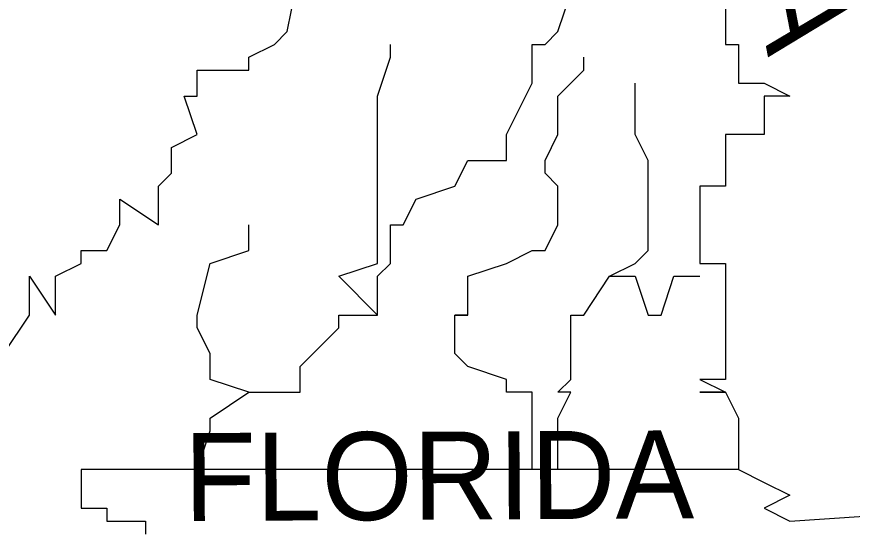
# Model space of a CAD drawing. Extents: x 515543 to 517243, y 661761 to 662861.
# Drawn here: x 516464.39 to 516481.42, y 661799.7 to 661810.2 of the extents above; entities that cross this region are included whole.
import ezdxf

# ---------------------------------------------------------------- set-up
doc = ezdxf.new("R2010")
doc.units = 0
doc.layers.add('great seal', color=7, linetype='Continuous')

msp = doc.modelspace()

# ---------------------------------------------------------------- linework, layer by layer
at = {"layer": 'great seal'}
for points in [[(516471.743, 661804.114), (516471.743, 661804.114), (516471.743, 661804.903), (516472.005, 661805.165), (516472.005, 661805.428), (516472.005, 661805.954), (516472.268, 661805.954), (516472.531, 661806.479), (516473.319, 661806.742), (516473.582, 661807.267), (516474.37, 661807.267), (516474.37, 661807.793), (516474.896, 661808.844), (516474.896, 661809.37), (516474.896, 661809.37), (516474.896, 661809.632), (516475.158, 661809.632), (516475.421, 661809.895), (516475.684, 661810.683), (516476.472, 661811.209), (516476.998, 661811.472), (516476.998, 661811.734), (516476.998, 661811.997), (516476.472, 661811.997)], [(516471.743, 661804.114), (516471.743, 661804.114), (516471.743, 661804.903), (516472.005, 661805.165), (516472.005, 661805.428), (516472.005, 661805.954), (516472.268, 661805.954), (516472.531, 661806.479), (516473.319, 661806.742), (516473.582, 661807.267), (516474.37, 661807.267), (516474.37, 661807.793), (516474.896, 661808.844), (516474.896, 661809.37), (516474.896, 661809.37), (516474.896, 661809.632), (516475.158, 661809.632), (516475.421, 661809.895), (516475.684, 661810.683), (516476.472, 661811.209), (516476.998, 661811.472), (516476.998, 661811.734), (516476.998, 661811.997), (516476.472, 661811.997)], [(516471.743, 661804.114), (516471.743, 661804.114), (516471.743, 661804.903), (516472.005, 661805.165), (516472.005, 661805.428), (516472.005, 661805.954), (516472.268, 661805.954), (516472.531, 661806.479), (516473.319, 661806.742), (516473.582, 661807.267), (516474.37, 661807.267), (516474.37, 661807.793), (516474.896, 661808.844), (516474.896, 661809.37), (516474.896, 661809.37), (516474.896, 661809.632), (516475.158, 661809.632), (516475.421, 661809.895), (516475.684, 661810.683), (516476.472, 661811.209), (516476.998, 661811.472), (516476.998, 661811.734), (516476.998, 661811.997), (516476.472, 661811.997)], [(516464.122, 661803.326), (516464.648, 661804.114), (516464.648, 661804.903), (516465.173, 661804.114), (516465.173, 661804.903), (516465.699, 661805.165), (516465.699, 661805.428), (516466.224, 661805.428), (516466.487, 661805.954), (516466.487, 661806.479), (516467.276, 661805.954), (516467.276, 661806.742), (516467.538, 661807.005), (516467.538, 661807.267), (516467.538, 661807.53), (516468.064, 661807.793), (516467.801, 661808.581), (516468.064, 661808.581), (516468.064, 661809.107), (516469.115, 661809.107), (516469.115, 661809.37), (516469.115, 661809.37), (516469.64, 661809.632), (516469.903, 661809.895), (516470.166, 661811.209)], [(516464.122, 661803.326), (516464.648, 661804.114), (516464.648, 661804.903), (516465.173, 661804.114), (516465.173, 661804.903), (516465.699, 661805.165), (516465.699, 661805.428), (516466.224, 661805.428), (516466.487, 661805.954), (516466.487, 661806.479), (516467.276, 661805.954), (516467.276, 661806.742), (516467.538, 661807.005), (516467.538, 661807.267), (516467.538, 661807.53), (516468.064, 661807.793), (516467.801, 661808.581), (516468.064, 661808.581), (516468.064, 661809.107), (516469.115, 661809.107), (516469.115, 661809.37), (516469.115, 661809.37), (516469.64, 661809.632), (516469.903, 661809.895), (516470.166, 661811.209)], [(516464.122, 661803.326), (516464.648, 661804.114), (516464.648, 661804.903), (516465.173, 661804.114), (516465.173, 661804.903), (516465.699, 661805.165), (516465.699, 661805.428), (516466.224, 661805.428), (516466.487, 661805.954), (516466.487, 661806.479), (516467.276, 661805.954), (516467.276, 661806.742), (516467.538, 661807.005), (516467.538, 661807.267), (516467.538, 661807.53), (516468.064, 661807.793), (516467.801, 661808.581), (516468.064, 661808.581), (516468.064, 661809.107), (516469.115, 661809.107), (516469.115, 661809.37), (516469.115, 661809.37), (516469.64, 661809.632), (516469.903, 661809.895), (516470.166, 661811.209)], [(516478.837, 661810.683), (516478.837, 661809.895), (516478.837, 661809.632), (516479.1, 661809.632), (516479.1, 661809.37), (516479.1, 661809.37), (516479.1, 661809.107), (516479.1, 661808.844), (516479.625, 661808.844), (516480.151, 661808.581), (516479.625, 661808.581), (516479.625, 661807.793), (516479.625, 661807.793), (516479.1, 661807.793), (516479.1, 661807.793), (516479.1, 661807.793), (516479.1, 661807.793), (516478.837, 661807.793), (516478.837, 661807.793), (516478.837, 661807.793), (516478.837, 661807.53), (516478.837, 661807.267), (516478.837, 661807.267), (516478.837, 661807.267), (516478.837, 661807.267), (516478.837, 661807.267), (516478.837, 661807.005), (516478.837, 661807.005), (516478.837, 661807.005), (516478.837, 661806.742), (516478.837, 661806.742), (516478.312, 661806.742), (516478.312, 661806.742), (516478.312, 661806.742), (516478.312, 661806.479), (516478.312, 661806.479), (516478.312, 661805.954), (516478.312, 661805.954), (516478.312, 661805.954), (516478.312, 661805.954), (516478.312, 661805.954), (516478.312, 661805.954), (516478.312, 661805.954), (516478.312, 661805.428), (516478.312, 661805.428), (516478.312, 661805.428), (516478.312, 661805.428), (516478.312, 661805.428), (516478.312, 661805.428), (516478.312, 661805.165), (516478.837, 661805.165), (516478.837, 661804.903), (516478.837, 661804.903), (516478.837, 661804.903), (516478.837, 661804.114), (516478.837, 661804.114), (516478.837, 661804.114), (516478.837, 661804.114), (516478.837, 661804.114), (516478.837, 661804.114), (516478.837, 661803.851), (516478.837, 661803.326), (516478.837, 661803.326), (516478.837, 661803.326), (516478.837, 661803.063), (516478.837, 661803.063), (516478.837, 661802.8), (516478.837, 661802.8), (516478.312, 661802.8), (516478.312, 661802.8), (516478.312, 661802.8), (516478.312, 661802.8), (516478.837, 661802.538), (516478.837, 661802.538), (516478.312, 661802.538), (516478.837, 661802.538), (516478.837, 661802.538), (516478.837, 661802.538), (516479.1, 661802.012), (516479.1, 661802.012), (516479.1, 661801.749), (516479.1, 661801.749), (516479.1, 661800.961), (516465.699, 661800.961), (516465.699, 661800.698), (516465.699, 661800.698)], [(516478.837, 661810.683), (516478.837, 661809.895), (516478.837, 661809.632), (516479.1, 661809.632), (516479.1, 661809.37), (516479.1, 661809.37), (516479.1, 661809.107), (516479.1, 661808.844), (516479.625, 661808.844), (516480.151, 661808.581), (516479.625, 661808.581), (516479.625, 661807.793), (516479.625, 661807.793), (516479.1, 661807.793), (516479.1, 661807.793), (516479.1, 661807.793), (516479.1, 661807.793), (516478.837, 661807.793), (516478.837, 661807.793), (516478.837, 661807.793), (516478.837, 661807.53), (516478.837, 661807.267), (516478.837, 661807.267), (516478.837, 661807.267), (516478.837, 661807.267), (516478.837, 661807.267), (516478.837, 661807.005), (516478.837, 661807.005), (516478.837, 661807.005), (516478.837, 661806.742), (516478.837, 661806.742), (516478.312, 661806.742), (516478.312, 661806.742), (516478.312, 661806.742), (516478.312, 661806.479), (516478.312, 661806.479), (516478.312, 661805.954), (516478.312, 661805.954), (516478.312, 661805.954), (516478.312, 661805.954), (516478.312, 661805.954), (516478.312, 661805.954), (516478.312, 661805.954), (516478.312, 661805.428), (516478.312, 661805.428), (516478.312, 661805.428), (516478.312, 661805.428), (516478.312, 661805.428), (516478.312, 661805.428), (516478.312, 661805.165), (516478.837, 661805.165), (516478.837, 661804.903), (516478.837, 661804.903), (516478.837, 661804.903), (516478.837, 661804.114), (516478.837, 661804.114), (516478.837, 661804.114), (516478.837, 661804.114), (516478.837, 661804.114), (516478.837, 661804.114), (516478.837, 661803.851), (516478.837, 661803.326), (516478.837, 661803.326), (516478.837, 661803.326), (516478.837, 661803.063), (516478.837, 661803.063), (516478.837, 661802.8), (516478.837, 661802.8), (516478.312, 661802.8), (516478.312, 661802.8), (516478.312, 661802.8), (516478.312, 661802.8), (516478.837, 661802.538), (516478.837, 661802.538), (516478.312, 661802.538), (516478.837, 661802.538), (516478.837, 661802.538), (516478.837, 661802.538), (516479.1, 661802.012), (516479.1, 661802.012), (516479.1, 661801.749), (516479.1, 661801.749), (516479.1, 661800.961), (516465.699, 661800.961), (516465.699, 661800.698), (516465.699, 661800.698)], [(516478.837, 661810.683), (516478.837, 661809.895), (516478.837, 661809.632), (516479.1, 661809.632), (516479.1, 661809.37), (516479.1, 661809.37), (516479.1, 661809.107), (516479.1, 661808.844), (516479.625, 661808.844), (516480.151, 661808.581), (516479.625, 661808.581), (516479.625, 661807.793), (516479.625, 661807.793), (516479.1, 661807.793), (516479.1, 661807.793), (516479.1, 661807.793), (516479.1, 661807.793), (516478.837, 661807.793), (516478.837, 661807.793), (516478.837, 661807.793), (516478.837, 661807.53), (516478.837, 661807.267), (516478.837, 661807.267), (516478.837, 661807.267), (516478.837, 661807.267), (516478.837, 661807.267), (516478.837, 661807.005), (516478.837, 661807.005), (516478.837, 661807.005), (516478.837, 661806.742), (516478.837, 661806.742), (516478.312, 661806.742), (516478.312, 661806.742), (516478.312, 661806.742), (516478.312, 661806.479), (516478.312, 661806.479), (516478.312, 661805.954), (516478.312, 661805.954), (516478.312, 661805.954), (516478.312, 661805.954), (516478.312, 661805.954), (516478.312, 661805.954), (516478.312, 661805.954), (516478.312, 661805.428), (516478.312, 661805.428), (516478.312, 661805.428), (516478.312, 661805.428), (516478.312, 661805.428), (516478.312, 661805.428), (516478.312, 661805.165), (516478.837, 661805.165), (516478.837, 661804.903), (516478.837, 661804.903), (516478.837, 661804.903), (516478.837, 661804.114), (516478.837, 661804.114), (516478.837, 661804.114), (516478.837, 661804.114), (516478.837, 661804.114), (516478.837, 661804.114), (516478.837, 661803.851), (516478.837, 661803.326), (516478.837, 661803.326), (516478.837, 661803.326), (516478.837, 661803.063), (516478.837, 661803.063), (516478.837, 661802.8), (516478.837, 661802.8), (516478.312, 661802.8), (516478.312, 661802.8), (516478.312, 661802.8), (516478.312, 661802.8), (516478.837, 661802.538), (516478.837, 661802.538), (516478.312, 661802.538), (516478.837, 661802.538), (516478.837, 661802.538), (516478.837, 661802.538), (516479.1, 661802.012), (516479.1, 661802.012), (516479.1, 661801.749), (516479.1, 661801.749), (516479.1, 661800.961), (516465.699, 661800.961), (516465.699, 661800.698), (516465.699, 661800.698)], [(516469.115, 661802.538), (516469.115, 661802.538), (516469.64, 661802.538), (516469.903, 661802.538), (516470.166, 661802.538), (516470.166, 661802.8), (516470.166, 661803.063), (516470.429, 661803.326), (516470.954, 661803.851), (516470.954, 661804.114), (516471.743, 661804.114), (516471.743, 661804.114), (516470.954, 661804.903), (516471.743, 661805.165), (516471.743, 661805.428), (516471.743, 661805.954), (516471.743, 661806.479), (516471.743, 661806.742), (516471.743, 661807.267), (516471.743, 661807.267), (516471.743, 661807.793), (516471.743, 661808.581), (516472.005, 661809.37), (516472.005, 661809.37), (516472.005, 661809.632)], [(516469.115, 661802.538), (516469.115, 661802.538), (516469.64, 661802.538), (516469.903, 661802.538), (516470.166, 661802.538), (516470.166, 661802.8), (516470.166, 661803.063), (516470.429, 661803.326), (516470.954, 661803.851), (516470.954, 661804.114), (516471.743, 661804.114), (516471.743, 661804.114), (516470.954, 661804.903), (516471.743, 661805.165), (516471.743, 661805.428), (516471.743, 661805.954), (516471.743, 661806.479), (516471.743, 661806.742), (516471.743, 661807.267), (516471.743, 661807.267), (516471.743, 661807.793), (516471.743, 661808.581), (516472.005, 661809.37), (516472.005, 661809.37), (516472.005, 661809.632)], [(516469.115, 661802.538), (516469.115, 661802.538), (516469.64, 661802.538), (516469.903, 661802.538), (516470.166, 661802.538), (516470.166, 661802.8), (516470.166, 661803.063), (516470.429, 661803.326), (516470.954, 661803.851), (516470.954, 661804.114), (516471.743, 661804.114), (516471.743, 661804.114), (516470.954, 661804.903), (516471.743, 661805.165), (516471.743, 661805.428), (516471.743, 661805.954), (516471.743, 661806.479), (516471.743, 661806.742), (516471.743, 661807.267), (516471.743, 661807.267), (516471.743, 661807.793), (516471.743, 661808.581), (516472.005, 661809.37), (516472.005, 661809.37), (516472.005, 661809.632)], [(516474.896, 661800.961), (516474.896, 661801.749), (516474.896, 661802.012), (516474.896, 661802.538), (516474.896, 661802.538), (516474.37, 661802.538), (516474.37, 661802.8), (516473.582, 661803.063), (516473.319, 661803.326), (516473.319, 661803.851), (516473.319, 661804.114), (516473.582, 661804.114), (516473.319, 661804.114), (516473.582, 661804.114), (516473.582, 661804.903), (516474.37, 661805.165), (516474.896, 661805.428), (516474.896, 661805.428), (516475.158, 661805.428), (516475.421, 661805.954), (516475.421, 661805.954), (516475.421, 661806.479), (516475.421, 661806.742), (516475.421, 661806.742), (516475.158, 661807.005), (516475.158, 661807.267), (516475.421, 661807.793), (516475.421, 661808.581), (516475.684, 661808.844), (516475.947, 661809.107), (516475.947, 661809.37)], [(516474.896, 661800.961), (516474.896, 661801.749), (516474.896, 661802.012), (516474.896, 661802.538), (516474.896, 661802.538), (516474.37, 661802.538), (516474.37, 661802.8), (516473.582, 661803.063), (516473.319, 661803.326), (516473.319, 661803.851), (516473.319, 661804.114), (516473.582, 661804.114), (516473.319, 661804.114), (516473.582, 661804.114), (516473.582, 661804.903), (516474.37, 661805.165), (516474.896, 661805.428), (516474.896, 661805.428), (516475.158, 661805.428), (516475.421, 661805.954), (516475.421, 661805.954), (516475.421, 661806.479), (516475.421, 661806.742), (516475.421, 661806.742), (516475.158, 661807.005), (516475.158, 661807.267), (516475.421, 661807.793), (516475.421, 661808.581), (516475.684, 661808.844), (516475.947, 661809.107), (516475.947, 661809.37)], [(516474.896, 661800.961), (516474.896, 661801.749), (516474.896, 661802.012), (516474.896, 661802.538), (516474.896, 661802.538), (516474.37, 661802.538), (516474.37, 661802.8), (516473.582, 661803.063), (516473.319, 661803.326), (516473.319, 661803.851), (516473.319, 661804.114), (516473.582, 661804.114), (516473.319, 661804.114), (516473.582, 661804.114), (516473.582, 661804.903), (516474.37, 661805.165), (516474.896, 661805.428), (516474.896, 661805.428), (516475.158, 661805.428), (516475.421, 661805.954), (516475.421, 661805.954), (516475.421, 661806.479), (516475.421, 661806.742), (516475.421, 661806.742), (516475.158, 661807.005), (516475.158, 661807.267), (516475.421, 661807.793), (516475.421, 661808.581), (516475.684, 661808.844), (516475.947, 661809.107), (516475.947, 661809.37)], [(516476.472, 661804.903), (516476.472, 661804.903), (516476.998, 661805.165), (516477.261, 661805.428), (516477.261, 661805.428), (516477.261, 661805.954), (516477.261, 661806.479), (516477.261, 661806.742), (516477.261, 661807.005), (516477.261, 661807.267), (516476.998, 661807.793), (516476.998, 661807.793), (516476.998, 661808.844)], [(516476.472, 661804.903), (516476.472, 661804.903), (516476.998, 661805.165), (516477.261, 661805.428), (516477.261, 661805.428), (516477.261, 661805.954), (516477.261, 661806.479), (516477.261, 661806.742), (516477.261, 661807.005), (516477.261, 661807.267), (516476.998, 661807.793), (516476.998, 661807.793), (516476.998, 661808.844)], [(516476.472, 661804.903), (516476.472, 661804.903), (516476.998, 661805.165), (516477.261, 661805.428), (516477.261, 661805.428), (516477.261, 661805.954), (516477.261, 661806.479), (516477.261, 661806.742), (516477.261, 661807.005), (516477.261, 661807.267), (516476.998, 661807.793), (516476.998, 661807.793), (516476.998, 661808.844)], [(516468.064, 661800.961), (516468.327, 661801.749), (516468.327, 661802.012), (516469.115, 661802.538), (516469.115, 661802.538), (516469.115, 661802.538), (516468.327, 661802.8), (516468.327, 661803.063), (516468.327, 661803.326), (516468.064, 661803.851), (516468.064, 661804.114), (516468.064, 661804.114), (516468.327, 661805.165), (516469.115, 661805.428), (516469.115, 661805.954)], [(516468.064, 661800.961), (516468.327, 661801.749), (516468.327, 661802.012), (516469.115, 661802.538), (516469.115, 661802.538), (516469.115, 661802.538), (516468.327, 661802.8), (516468.327, 661803.063), (516468.327, 661803.326), (516468.064, 661803.851), (516468.064, 661804.114), (516468.064, 661804.114), (516468.327, 661805.165), (516469.115, 661805.428), (516469.115, 661805.954)], [(516468.064, 661800.961), (516468.327, 661801.749), (516468.327, 661802.012), (516469.115, 661802.538), (516469.115, 661802.538), (516469.115, 661802.538), (516468.327, 661802.8), (516468.327, 661803.063), (516468.327, 661803.326), (516468.064, 661803.851), (516468.064, 661804.114), (516468.064, 661804.114), (516468.327, 661805.165), (516469.115, 661805.428), (516469.115, 661805.954)], [(516475.421, 661800.961), (516475.421, 661801.749), (516475.421, 661801.749), (516475.421, 661802.012), (516475.684, 661802.538), (516475.421, 661802.538), (516475.684, 661802.8), (516475.684, 661803.063), (516475.684, 661803.326), (516475.684, 661803.326), (516475.684, 661803.851), (516475.684, 661804.114), (516475.947, 661804.114), (516476.472, 661804.903), (516476.998, 661804.903), (516477.261, 661804.114), (516477.523, 661804.114), (516477.786, 661804.903), (516478.049, 661804.903), (516478.312, 661804.903)], [(516475.421, 661800.961), (516475.421, 661801.749), (516475.421, 661801.749), (516475.421, 661802.012), (516475.684, 661802.538), (516475.421, 661802.538), (516475.684, 661802.8), (516475.684, 661803.063), (516475.684, 661803.326), (516475.684, 661803.326), (516475.684, 661803.851), (516475.684, 661804.114), (516475.947, 661804.114), (516476.472, 661804.903), (516476.998, 661804.903), (516477.261, 661804.114), (516477.523, 661804.114), (516477.786, 661804.903), (516478.049, 661804.903), (516478.312, 661804.903)], [(516475.421, 661800.961), (516475.421, 661801.749), (516475.421, 661801.749), (516475.421, 661802.012), (516475.684, 661802.538), (516475.421, 661802.538), (516475.684, 661802.8), (516475.684, 661803.063), (516475.684, 661803.326), (516475.684, 661803.326), (516475.684, 661803.851), (516475.684, 661804.114), (516475.947, 661804.114), (516476.472, 661804.903), (516476.998, 661804.903), (516477.261, 661804.114), (516477.523, 661804.114), (516477.786, 661804.903), (516478.049, 661804.903), (516478.312, 661804.903)], [(516479.1, 661800.961), (516479.625, 661800.698), (516479.625, 661800.698), (516480.151, 661800.436), (516479.625, 661800.173), (516480.151, 661799.91), (516484.092, 661800.173)], [(516479.1, 661800.961), (516479.625, 661800.698), (516479.625, 661800.698), (516480.151, 661800.436), (516479.625, 661800.173), (516480.151, 661799.91), (516484.092, 661800.173)], [(516479.1, 661800.961), (516479.625, 661800.698), (516479.625, 661800.698), (516480.151, 661800.436), (516479.625, 661800.173), (516480.151, 661799.91), (516484.092, 661800.173)], [(516465.699, 661800.698), (516465.699, 661800.436), (516465.699, 661800.436), (516465.699, 661800.173), (516465.699, 661800.173), (516466.224, 661800.173), (516466.224, 661800.173), (516466.224, 661799.91), (516466.487, 661799.91), (516466.487, 661799.91), (516466.487, 661799.91), (516467.013, 661799.91), (516467.013, 661799.91), (516467.013, 661799.91), (516467.013, 661799.647)], [(516465.699, 661800.698), (516465.699, 661800.436), (516465.699, 661800.436), (516465.699, 661800.173), (516465.699, 661800.173), (516466.224, 661800.173), (516466.224, 661800.173), (516466.224, 661799.91), (516466.487, 661799.91), (516466.487, 661799.91), (516466.487, 661799.91), (516467.013, 661799.91), (516467.013, 661799.91), (516467.013, 661799.91), (516467.013, 661799.647)], [(516465.699, 661800.698), (516465.699, 661800.436), (516465.699, 661800.436), (516465.699, 661800.173), (516465.699, 661800.173), (516466.224, 661800.173), (516466.224, 661800.173), (516466.224, 661799.91), (516466.487, 661799.91), (516466.487, 661799.91), (516466.487, 661799.91), (516467.013, 661799.91), (516467.013, 661799.91), (516467.013, 661799.91), (516467.013, 661799.647)]]:
    msp.add_lwpolyline(points, dxfattribs=at)
for radius in [22.994, 22.994, 22.994, 22.389, 22.389, 22.389, 17.779, 17.779, 17.779, 17.222, 17.222, 17.222]:
    msp.add_circle((516470.184, 661810.762), radius, dxfattribs=at)

# ---------------------------------------------------------------- texts
for s, height, rotation, p in [('GEORGIA', 1.8446, 280.9296, (516477.523, 661820.668)), ('GEORGIA', 1.8446, 280.9296, (516477.523, 661820.668)), ('GEORGIA', 1.8446, 280.9296, (516477.523, 661820.668)), ('FLORIDA', 1.7942, 0.3238, (516467.801, 661799.91)), ('FLORIDA', 1.7942, 0.3238, (516467.801, 661799.91)), ('FLORIDA', 1.7942, 0.3238, (516467.801, 661799.91))]:
    msp.add_text(s, height=height, rotation=rotation, dxfattribs=at).set_placement(p)

doc.saveas('drawing.dxf')
